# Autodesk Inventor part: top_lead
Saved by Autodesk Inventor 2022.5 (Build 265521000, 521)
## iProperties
Created: 2024-12
Part Number: top_lead
Material: Generic
Document SubType Name: Modeling
Designer: AdminForWorker
Density: 1 g/cm^3
Appearance: Default
Title: top_lead
Author: AdminForWorker
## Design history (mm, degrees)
feature "Body1"
body "Solid1"
